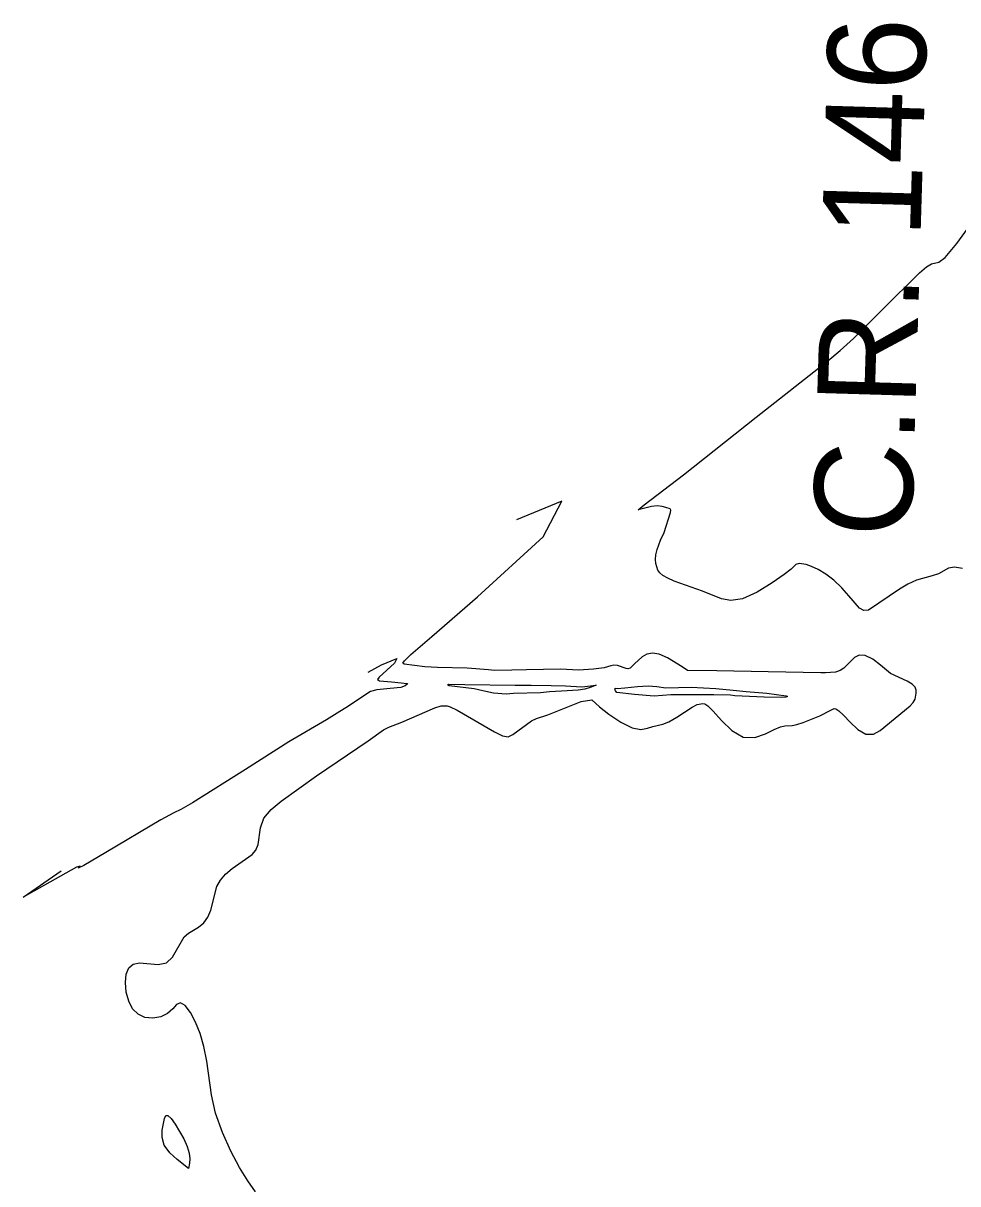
# Model space of a CAD drawing. Extents: x -468541894 to 3393103, y -306086142 to 1227927.
# Drawn here: x 1845353 to 1845797, y 539185 to 539736 of the extents above; entities that cross this region are included whole.
import ezdxf

# ---------------------------------------------------------------- set-up
doc = ezdxf.new("R2010")
doc.units = 0
doc.layers.add('DT_X_Contour_Minor', color=7, linetype='Continuous')
doc.layers.add('Level 40', color=7, linetype='Continuous')

msp = doc.modelspace()

# ---------------------------------------------------------------- linework, layer by layer
at = {"layer": 'DT_X_Contour_Minor'}
for points in [[(1845647.54, 539507.35), (1845666.21, 539521.65), (1845700.82, 539548.98), (1845734.85, 539575.72), (1845740.65, 539580.62), (1845746.93, 539586.46), (1845760.74, 539600.15), (1845778.34, 539617.63), (1845781.74, 539620.51), (1845784.04, 539621.93), (1845787.56, 539622.71), (1845790.6, 539624.95), (1845796.15, 539631.46), (1845814.58, 539657.1)], [(1845712.31, 539401.83), (1845714.41, 539402.27), (1845717.88, 539402.5), (1845720.06, 539402.94), (1845723.01, 539403.86), (1845730.92, 539407.13), (1845736.22, 539409.82), (1845737.8, 539410.61), (1845738.64, 539410.41), (1845740.03, 539409.49), (1845742.23, 539407.42), (1845745.35, 539404.09), (1845749.07, 539400.6), (1845752.91, 539398.37), (1845756.48, 539398.41), (1845759.73, 539400.11), (1845773.89, 539411.8), (1845775.33, 539413.4), (1845776.21, 539414.96), (1845776.8, 539417.92), (1845776.77, 539419.34), (1845776.26, 539420.73), (1845774.87, 539422.15), (1845772.42, 539423.58), (1845764.49, 539427.24), (1845759.87, 539431.18), (1845756.15, 539433.94), (1845752.52, 539435.81), (1845749.62, 539435.98), (1845747.39, 539434.84), (1845742.42, 539429.74), (1845740.61, 539428.57), (1845738.5, 539427.89), (1845733.7, 539427.45), (1845731.47, 539427.51), (1845706.41, 539427.94), (1845682.01, 539428.54), (1845668.17, 539428.66), (1845665.56, 539430.3), (1845658.58, 539434.64), (1845654.71, 539436.37), (1845651.43, 539436.9), (1845648.75, 539436.38), (1845646.52, 539435.14), (1845642.99, 539431.85), (1845640.82, 539429.72), (1845639.8, 539429.36), (1845639.03, 539429.56), (1845634.82, 539430.94), (1845633.07, 539431.16), (1845631.64, 539430.92), (1845628.51, 539429.83), (1845623.51, 539429.19), (1845616.28, 539428.87), (1845607.81, 539429.19), (1845591.63, 539428.97), (1845584.67, 539428.83), (1845576.42, 539428.56), (1845573.62, 539428.94), (1845563.45, 539429.71), (1845549.42, 539430), (1845543.33, 539430.3), (1845533.61, 539431.61), (1845532.97, 539432.13), (1845533.67, 539433.29), (1845536.78, 539436.17), (1845546.62, 539444.72), (1845568.3, 539463.57), (1845599.54, 539492.16), (1845608.47, 539509.02), (1845586.91, 539500.2)], [(1845798.82, 539477.18), (1845794.95, 539477.77), (1845792.08, 539477.19), (1845787.41, 539474.58), (1845784.37, 539473.61), (1845776.87, 539471.55), (1845772.86, 539469.7), (1845768.83, 539467.28), (1845754.18, 539457.35), (1845751.88, 539457.12), (1845749.91, 539458.28), (1845744.82, 539464.05), (1845741.38, 539467.9), (1845737.64, 539471.55), (1845733.82, 539474.48), (1845730.18, 539476.64), (1845727, 539478.11), (1845724.45, 539478.97), (1845721.16, 539479.4), (1845719.66, 539478.97), (1845717.4, 539476.83), (1845714.08, 539474.33), (1845708.28, 539470.3), (1845701.15, 539465.9), (1845694.25, 539462.7), (1845688.75, 539461.83), (1845684.26, 539462.74), (1845675.23, 539466.26), (1845661.85, 539471.06), (1845658.73, 539472.5), (1845656.43, 539473.84), (1845654.95, 539475.09), (1845654.06, 539476.36), (1845653.11, 539479.46), (1845652.91, 539481.42), (1845653.07, 539483.67), (1845653.66, 539486.14), (1845655.34, 539490.52), (1845657.06, 539494.17), (1845660.09, 539503.68), (1845660.2, 539504.78), (1845659.86, 539505.4), (1845657.78, 539506.04), (1845656.05, 539506.5), (1845653.8, 539506.81), (1845650.96, 539506.59), (1845644.72, 539505.02), (1845647.54, 539507.35)], [(1845516.4, 539427.8), (1845522.85, 539431.4), (1845530.11, 539434.37), (1845528.88, 539432.05), (1845521.66, 539425.5), (1845520.84, 539424.28), (1845521.86, 539423.79), (1845527.49, 539423.18), (1845535.1, 539422.46), (1845535.02, 539422.15), (1845533.95, 539421.32), (1845532.01, 539420.57), (1845526.95, 539420.02), (1845520.52, 539419.48), (1845517.49, 539418.68), (1845514.88, 539416.98)], [(1845624.67, 539421.6), (1845621.82, 539420.52), (1845619.39, 539419.82), (1845616.15, 539419.24), (1845608.22, 539418.8), (1845602.54, 539418.44), (1845598.29, 539417.98), (1845585.43, 539417.73), (1845582.02, 539417.37), (1845575.98, 539417.9), (1845570.93, 539418.92), (1845566.76, 539419.9), (1845554.88, 539421.31), (1845554.13, 539421.9), (1845554.53, 539422.08), (1845562.36, 539422.04), (1845586.2, 539421.63), (1845593.93, 539421.62), (1845603.41, 539421.49), (1845610.18, 539421.3), (1845617.87, 539420.91), (1845624.67, 539421.6)], [(1845644.34, 539421.1), (1845649.37, 539421.38), (1845653.53, 539421.04), (1845657.85, 539420.44), (1845663.92, 539420.52), (1845669.91, 539420.66), (1845681.63, 539420.14), (1845689.86, 539419.21), (1845696.04, 539418.65), (1845705.86, 539417.9), (1845715, 539416.62), (1845715.61, 539416.31), (1845714.87, 539416.03), (1845712.72, 539415.83), (1845704.6, 539415.89), (1845690.59, 539416.62), (1845688.62, 539416.87), (1845680.65, 539417.09), (1845660.16, 539417.09), (1845652.25, 539416.37), (1845642.93, 539417.16), (1845634.56, 539418.14), (1845633.88, 539418.9), (1845633.65, 539419.87), (1845633.76, 539420.16), (1845634.78, 539420.15), (1845638.32, 539420.32), (1845644.34, 539421.1)], [(1845514.88, 539416.98), (1845507.1, 539411.7), (1845501.78, 539408.34), (1845496.57, 539405.22), (1845478.79, 539394.76), (1845458.1, 539381.54), (1845433, 539365.68), (1845427.49, 539362.55), (1845424.15, 539360.97), (1845418, 539357.67), (1845391.77, 539342.12), (1845381.45, 539336.05), (1845378.74, 539334.77), (1845379.58, 539335.73), (1845377.95, 539335.17), (1845352.58, 539320.96), (1845370.57, 539333.41)], [(1845462.86, 539180.84), (1845459.23, 539186.18), (1845455.36, 539192.47), (1845451.18, 539200.28), (1845447.17, 539209.11), (1845443.96, 539218.25), (1845441.98, 539227.07), (1845439.78, 539243.01), (1845438.4, 539249.96), (1845436.6, 539256.16), (1845434.44, 539261.59), (1845432.01, 539266.14), (1845429.55, 539269.37), (1845427.32, 539270.74), (1845425.46, 539269.96), (1845423.58, 539267.88), (1845421.17, 539265.58), (1845417.88, 539264.01), (1845414.09, 539263.4), (1845410.35, 539263.82), (1845407.12, 539265.34), (1845404.55, 539267.9), (1845402.68, 539271.43), (1845401.55, 539275.77), (1845401.18, 539280.31), (1845401.56, 539284.36), (1845402.71, 539287.34), (1845404.76, 539289.12), (1845407.88, 539289.73), (1845416.61, 539288.97), (1845420.64, 539289.72), (1845423.54, 539292.37), (1845429.07, 539302.13), (1845431.08, 539303.79), (1845435.87, 539306.71), (1845438.32, 539308.72), (1845440.35, 539311.39), (1845441.72, 539314.81), (1845444.62, 539325.93), (1845446.25, 539329.02), (1845448.63, 539331.88), (1845451.87, 539334.56), (1845461.38, 539341.2), (1845463.12, 539343.29), (1845464.11, 539346.01), (1845465.22, 539353.95), (1845466.94, 539358.39), (1845470.35, 539362.6), (1845475.1, 539366.62), (1845491.97, 539378.6), (1845516.39, 539395.18), (1845523.66, 539400.39), (1845526.22, 539401.72), (1845532.4, 539404.03), (1845548.16, 539410.9), (1845551.19, 539411.83), (1845553.41, 539411.83), (1845554.03, 539411.79), (1845555.46, 539411.35), (1845558.65, 539409.75), (1845576.39, 539399.43), (1845580.3, 539397.55), (1845582.89, 539397.19), (1845585.2, 539398.16), (1845593.97, 539404.69), (1845596.41, 539405.87), (1845601.74, 539407.51), (1845617.58, 539413.91), (1845622.63, 539414.63), (1845626.28, 539411.44), (1845630.8, 539407.93), (1845636.4, 539404.12), (1845641.8, 539401.36), (1845646.02, 539400.58), (1845649.18, 539401.16), (1845651.69, 539402.1), (1845656.37, 539403.14), (1845659.33, 539404.27), (1845663.05, 539406.4), (1845670.39, 539411.19), (1845672.76, 539412.42), (1845675.35, 539412.91), (1845676.37, 539412.77), (1845677.87, 539411.85), (1845680.38, 539409.34), (1845684.26, 539404.93), (1845689.19, 539400.14), (1845694.64, 539396.94), (1845700.12, 539396.72), (1845705.18, 539398.48), (1845709.34, 539400.6), (1845712.31, 539401.83)], [(1845431.1, 539192), (1845425.71, 539196.23), (1845422.28, 539199.45), (1845419.6, 539203.08), (1845418.52, 539206.75), (1845418.64, 539210.22), (1845419.77, 539215.69), (1845420.37, 539217.11), (1845421.34, 539217.19), (1845422.88, 539215.7), (1845424.82, 539213.02), (1845428.81, 539206.03), (1845430.39, 539202.49), (1845431.4, 539199.26), (1845431.74, 539196.57), (1845431.62, 539194.49), (1845431.1, 539192)]]:
    msp.add_lwpolyline(points, dxfattribs=at)

# ---------------------------------------------------------------- texts
at = {"layer": 'Level 40'}
msp.add_text('C.R. 146', height=46.8, rotation=88.2904, dxfattribs=at).set_placement((1845774.55, 539491.45))

doc.saveas('drawing.dxf')
